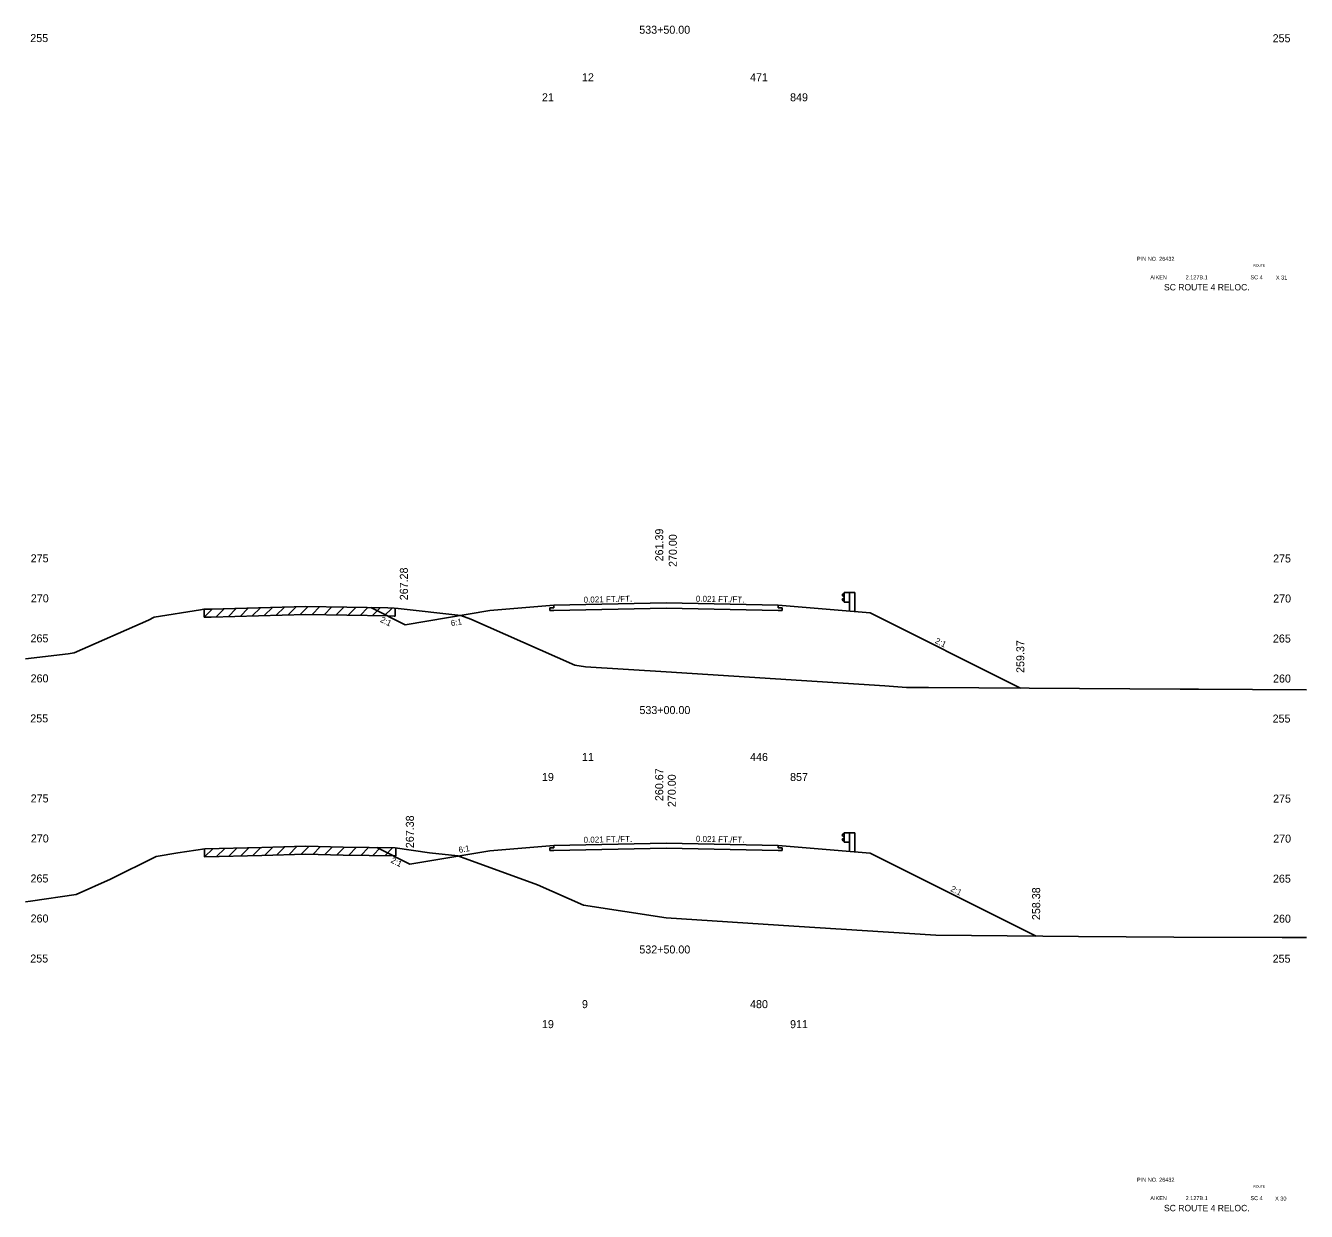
# Model space of a CAD drawing. Extents: x 2967 to 4323, y -3677 to -817.
# Drawn here: x 3555.3 to 3715.3, y -3120.9 to -2972.7 of the extents above; entities that cross this region are included whole.
import ezdxf

# ---------------------------------------------------------------- set-up
doc = ezdxf.new("R2010")
doc.units = 0
for name, color, linetype in [('Level 1', 7, 'Continuous'), ('Level 10', 7, 'Continuous'), ('Level 11', 7, 'Continuous'), ('Level 12', 7, 'Continuous'), ('Level 20', 7, 'Continuous'), ('Level 24', 7, 'Continuous'), ('Level 3', 7, 'Continuous'), ('Level 32', 7, 'Continuous'), ('Level 33', 7, 'Continuous'), ('Level 59', 7, 'Continuous'), ('Level 6', 7, 'Continuous'), ('Level 60', 7, 'Continuous'), ('Level 61', 7, 'Continuous'), ('Level 7', 7, 'Continuous')]:
    doc.layers.add(name, color=color, linetype=linetype)

msp = doc.modelspace()

# ---------------------------------------------------------------- linework, layer by layer
at = {"layer": 'Level 11'}
for p, q in [((3621.35, -3045.43), (3620.85, -3045.44)), ((3620.85, -3045.44), (3620.85, -3045.78)), ((3620.85, -3045.78), (3621.35, -3045.77)), ((3621.35, -3045.13), (3621.35, -3045.43)), ((3649.35, -3045.43), (3649.35, -3045.13)), ((3649.85, -3045.44), (3649.35, -3045.43)), ((3649.35, -3045.77), (3649.85, -3045.78)), ((3649.85, -3045.78), (3649.85, -3045.44)), ((3621.35, -3075.13), (3621.35, -3075.43)), ((3649.35, -3075.43), (3649.35, -3075.13)), ((3621.35, -3075.43), (3620.85, -3075.44)), ((3620.85, -3075.44), (3620.85, -3075.78)), ((3620.85, -3075.78), (3621.35, -3075.77)), ((3649.85, -3075.44), (3649.35, -3075.43)), ((3649.35, -3075.77), (3649.85, -3075.78)), ((3649.85, -3075.78), (3649.85, -3075.44))]:
    msp.add_line(p, q, dxfattribs=at)
at = {"layer": 'Level 12'}
for p, q in [((3635.35, -3045.48), (3621.35, -3045.77)), ((3649.35, -3045.77), (3635.35, -3045.48)), ((3635.35, -3075.48), (3621.35, -3075.77)), ((3649.35, -3075.77), (3635.35, -3075.48))]:
    msp.add_line(p, q, dxfattribs=at)
at = {"layer": 'Level 24'}
for p, q in [((3657.62, -3043.62), (3657.35, -3043.82)), ((3657.35, -3043.82), (3657.35, -3043.87)), ((3657.35, -3043.87), (3657.62, -3044.07)), ((3657.35, -3044.39), (3657.62, -3044.19)), ((3657.35, -3044.44), (3657.35, -3044.39)), ((3657.62, -3044.64), (3657.35, -3044.44)), ((3657.62, -3044.72), (3657.62, -3043.55)), ((3657.62, -3043.55), (3658.28, -3043.55)), ((3657.62, -3044.72), (3658.29, -3044.72)), ((3658.28, -3043.55), (3658.28, -3045.88)), ((3658.28, -3043.55), (3658.95, -3043.55)), ((3658.95, -3043.55), (3658.95, -3045.93)), ((3657.62, -3074.72), (3657.62, -3073.55)), ((3657.62, -3073.55), (3658.28, -3073.55)), ((3658.28, -3073.55), (3658.28, -3075.88)), ((3658.28, -3073.55), (3658.95, -3073.55)), ((3658.95, -3073.55), (3658.95, -3075.93)), ((3657.62, -3073.62), (3657.35, -3073.82)), ((3657.35, -3073.82), (3657.35, -3073.87)), ((3657.35, -3073.87), (3657.62, -3074.07)), ((3657.35, -3074.39), (3657.62, -3074.19)), ((3657.35, -3074.44), (3657.35, -3074.39)), ((3657.62, -3074.64), (3657.35, -3074.44)), ((3657.62, -3074.72), (3658.29, -3074.72))]:
    msp.add_line(p, q, dxfattribs=at)
at = {"layer": 'Level 59'}
for p, q in [((3621.35, -3045.13), (3635.35, -3044.84)), ((3635.35, -3044.84), (3649.35, -3045.13)), ((3621.35, -3075.13), (3635.35, -3074.84)), ((3635.35, -3074.84), (3649.35, -3075.13))]:
    msp.add_line(p, q, dxfattribs=at)
at = {"layer": 'Level 6'}
for p, q in [((3613.35, -3045.8), (3621.35, -3045.13)), ((3649.35, -3045.13), (3660.85, -3046.09)), ((3660.85, -3046.09), (3679.62, -3055.48)), ((3613.35, -3075.8), (3621.35, -3075.13)), ((3649.35, -3075.13), (3657.35, -3075.8)), ((3657.35, -3075.8), (3660.85, -3076.09))]:
    msp.add_line(p, q, dxfattribs=at)
at = {"layer": 'Level 60'}
for p, q in [((3571.4, -3046.62), (3577.2, -3045.7)), ((3577.2, -3045.7), (3577.63, -3045.63)), ((3577.63, -3045.63), (3578.51, -3045.61)), ((3578.51, -3045.61), (3590.34, -3045.27)), ((3590.34, -3045.27), (3600.59, -3045.46)), ((3600.59, -3045.46), (3601.38, -3045.48)), ((3601.38, -3045.48), (3601.9, -3045.55)), ((3601.9, -3045.55), (3609.72, -3046.41)), ((3561.4, -3051.07), (3570.68, -3046.98)), ((3570.68, -3046.98), (3571.4, -3046.62)), ((3609.72, -3046.41), (3610.98, -3046.86)), ((3610.98, -3046.86), (3623.94, -3052.6)), ((3555.35, -3051.8), (3560.66, -3051.18)), ((3560.66, -3051.18), (3561.4, -3051.07)), ((3623.94, -3052.6), (3625.3, -3052.81)), ((3625.3, -3052.81), (3635.35, -3053.45)), ((3635.35, -3053.45), (3662.7, -3055.2)), ((3662.7, -3055.2), (3665.41, -3055.38)), ((3665.41, -3055.38), (3668.13, -3055.4)), ((3668.13, -3055.4), (3699.57, -3055.6)), ((3699.57, -3055.6), (3701.85, -3055.61)), ((3701.85, -3055.61), (3715.35, -3055.68)), ((3565.96, -3079.35), (3571.65, -3076.5)), ((3571.65, -3076.5), (3574.35, -3076.07)), ((3574.35, -3076.07), (3577.73, -3075.57)), ((3577.73, -3075.57), (3584.85, -3075.4)), ((3584.85, -3075.4), (3590.3, -3075.24)), ((3590.3, -3075.24), (3595.03, -3075.33)), ((3595.03, -3075.33), (3601.52, -3075.44)), ((3601.52, -3075.44), (3605.79, -3076.06)), ((3605.79, -3076.06), (3609.35, -3076.45)), ((3609.35, -3076.45), (3619.31, -3080.06)), ((3561.66, -3081.25), (3565.96, -3079.35)), ((3555.96, -3082.1), (3561.66, -3081.25)), ((3619.31, -3080.06), (3625.04, -3082.6)), ((3555.35, -3082.17), (3555.96, -3082.1)), ((3625.04, -3082.6), (3635.35, -3084.18)), ((3635.35, -3084.18), (3651.31, -3085.2)), ((3651.31, -3085.2), (3669.07, -3086.34)), ((3669.07, -3086.34), (3686.89, -3086.51)), ((3686.89, -3086.51), (3698.8, -3086.59)), ((3698.8, -3086.59), (3712.32, -3086.62)), ((3712.32, -3086.62), (3715.35, -3086.64))]:
    msp.add_line(p, q, dxfattribs=at)
at = {"layer": 'Level 61'}
for p, q in [((3578.66, -3045.61), (3577.64, -3046.63)), ((3577.64, -3045.63), (3577.64, -3046.63)), ((3578.51, -3046.61), (3590.34, -3046.27)), ((3580.17, -3045.56), (3579.14, -3046.59)), ((3581.67, -3045.52), (3580.64, -3046.55)), ((3583.17, -3045.48), (3582.14, -3046.51)), ((3584.67, -3045.43), (3583.64, -3046.46)), ((3586.17, -3045.39), (3585.14, -3046.42)), ((3587.67, -3045.35), (3586.64, -3046.37)), ((3589.17, -3045.3), (3588.14, -3046.33)), ((3590.65, -3045.27), (3589.64, -3046.29)), ((3590.34, -3046.27), (3600.59, -3046.46)), ((3592.12, -3045.3), (3591.14, -3046.28)), ((3593.62, -3045.33), (3592.64, -3046.31)), ((3595.12, -3045.36), (3594.14, -3046.34)), ((3596.62, -3045.39), (3595.64, -3046.37)), ((3598.12, -3045.42), (3597.14, -3046.4)), ((3599.62, -3045.44), (3598.64, -3046.43)), ((3601.12, -3045.47), (3600.14, -3046.45)), ((3601.53, -3046.5), (3601.53, -3045.5)), ((3577.64, -3046.63), (3578.51, -3046.61)), ((3600.59, -3046.46), (3601.38, -3046.48)), ((3601.38, -3046.48), (3601.53, -3046.5)), ((3578.74, -3075.54), (3577.71, -3076.57)), ((3577.71, -3075.57), (3577.71, -3076.57)), ((3577.71, -3076.57), (3577.73, -3076.57)), ((3577.73, -3076.57), (3584.85, -3076.4)), ((3580.23, -3075.51), (3579.21, -3076.53)), ((3581.73, -3075.47), (3580.71, -3076.5)), ((3583.23, -3075.43), (3582.21, -3076.46)), ((3584.73, -3075.4), (3583.71, -3076.42)), ((3584.85, -3076.4), (3590.3, -3076.24)), ((3586.24, -3075.36), (3585.21, -3076.39)), ((3587.74, -3075.31), (3586.71, -3076.34)), ((3589.24, -3075.27), (3588.21, -3076.3)), ((3590.72, -3075.25), (3589.71, -3076.25)), ((3590.3, -3076.24), (3595.03, -3076.33)), ((3592.19, -3075.27), (3591.21, -3076.25)), ((3593.69, -3075.3), (3592.71, -3076.28)), ((3595.19, -3075.33), (3594.21, -3076.31)), ((3595.03, -3076.33), (3601.52, -3076.44)), ((3596.69, -3075.36), (3595.71, -3076.34)), ((3598.19, -3075.38), (3597.21, -3076.37)), ((3599.69, -3075.41), (3598.71, -3076.39)), ((3601.19, -3075.44), (3600.21, -3076.42)), ((3601.52, -3076.44), (3601.59, -3076.45)), ((3601.59, -3076.45), (3601.59, -3075.45))]:
    msp.add_line(p, q, dxfattribs=at)
at = {"layer": 'Level 7'}
for p, q in [((3598.46, -3045.42), (3602.75, -3047.57)), ((3602.75, -3047.57), (3613.35, -3045.8)), ((3599.22, -3075.4), (3603.35, -3077.47)), ((3603.35, -3077.47), (3613.35, -3075.8)), ((3660.85, -3076.09), (3681.59, -3086.46))]:
    msp.add_line(p, q, dxfattribs=at)

# ---------------------------------------------------------------- texts
at = {"layer": 'Level 1'}
for s, p in [('12', (3624.85, -2979.66)), ('471', (3645.85, -2979.66)), ('21', (3619.85, -2982.16)), ('849', (3650.85, -2982.16)), ('11', (3624.85, -3064.58)), ('446', (3645.85, -3064.58)), ('19', (3619.85, -3067.08)), ('857', (3650.85, -3067.08)), ('9', (3624.85, -3095.46)), ('480', (3645.85, -3095.46)), ('19', (3619.85, -3097.96)), ('911', (3650.85, -3097.96))]:
    msp.add_text(s, height=1, dxfattribs=at).set_placement(p)
at = {"layer": 'Level 10'}
for s, p in [('533+50.00', (3632.01, -2973.72)), ('533+00.00', (3632.03, -3058.72)), ('532+50.00', (3632.02, -3088.63))]:
    msp.add_text(s, height=1, dxfattribs=at).set_placement(p)
for s, p in [('261.39', (3635, -3039.64)), ('260.67', (3635, -3069.59))]:
    msp.add_text(s, height=1, rotation=90, dxfattribs=at).set_placement(p)
at = {"layer": 'Level 20'}
for s, height, p in [('PIN NO. 26432', 0.5, (3694.19, -3002.09)), ('ROUTE', 0.3, (3708.73, -3002.83)), ('AIKEN', 0.5, (3695.85, -3004.4)), (' 2.127B.1', 0.5, (3700.07, -3004.4)), ('SC 4', 0.5, (3708.36, -3004.4)), ('X 31', 0.5, (3711.54, -3004.43)), ('SC ROUTE 4 RELOC.', 0.8, (3697.56, -3005.79)), ('PIN NO. 26432', 0.5, (3694.19, -3117.15)), ('ROUTE', 0.3, (3708.73, -3117.89)), ('AIKEN', 0.5, (3695.85, -3119.45)), (' 2.127B.1', 0.5, (3700.07, -3119.45)), ('SC 4', 0.5, (3708.36, -3119.45)), ('X 30', 0.5, (3711.44, -3119.5)), ('SC ROUTE 4 RELOC.', 0.8, (3697.56, -3120.84))]:
    msp.add_text(s, height=height, dxfattribs=at).set_placement(p)
at = {"layer": 'Level 3'}
for s, p in [(' 255', (3555.56, -2974.76)), (' 255', (3710.76, -2974.78)), (' 275', (3555.61, -3039.76)), (' 275', (3710.82, -3039.78)), (' 270', (3555.63, -3044.76)), (' 270', (3710.83, -3044.78)), (' 265', (3555.59, -3049.76)), (' 265', (3710.8, -3049.78)), (' 260', (3555.6, -3054.76)), (' 260', (3710.81, -3054.78)), (' 255', (3555.56, -3059.76)), (' 255', (3710.76, -3059.78)), (' 275', (3555.61, -3069.76)), (' 275', (3710.82, -3069.78)), (' 270', (3555.63, -3074.76)), (' 270', (3710.83, -3074.78)), (' 265', (3555.59, -3079.76)), (' 265', (3710.8, -3079.78)), (' 260', (3555.6, -3084.76)), (' 260', (3710.81, -3084.78)), (' 255', (3555.56, -3089.76)), (' 255', (3710.76, -3089.78))]:
    msp.add_text(s, height=1, dxfattribs=at).set_placement(p)
at = {"layer": 'Level 32'}
for s, rotation, p in [('0.021 FT./FT.', 1.1916, (3625.06, -3044.81)), ('0.021 FT./FT.', 358.8084, (3639.07, -3044.67)), ('2:1', 333.435, (3599.58, -3047.17)), ('6:1', 9.4623, (3608.53, -3047.74)), ('2:1', 333.435, (3668.88, -3049.81)), ('6:1', 9.4623, (3609.5, -3076.06)), ('0.021 FT./FT.', 1.1916, (3625.06, -3074.81)), ('0.021 FT./FT.', 358.8084, (3639.07, -3074.67)), ('2:1', 333.435, (3600.89, -3077.23)), ('2:1', 333.435, (3670.82, -3080.8))]:
    msp.add_text(s, height=0.75, rotation=rotation, dxfattribs=at).set_placement(p)
at = {"layer": 'Level 33'}
for s, p in [('267.28', (3603.1, -3044.5)), ('259.37', (3680.11, -3053.58)), ('267.38', (3603.85, -3075.47)), ('258.38', (3682.09, -3084.46))]:
    msp.add_text(s, height=1, rotation=90, dxfattribs=at).set_placement(p)
at = {"layer": 'Level 59'}
for p in [(3636.7, -3040.71), (3636.57, -3070.71)]:
    msp.add_text(' 270.00', height=1, rotation=90, dxfattribs=at).set_placement(p)

doc.saveas('drawing.dxf')
